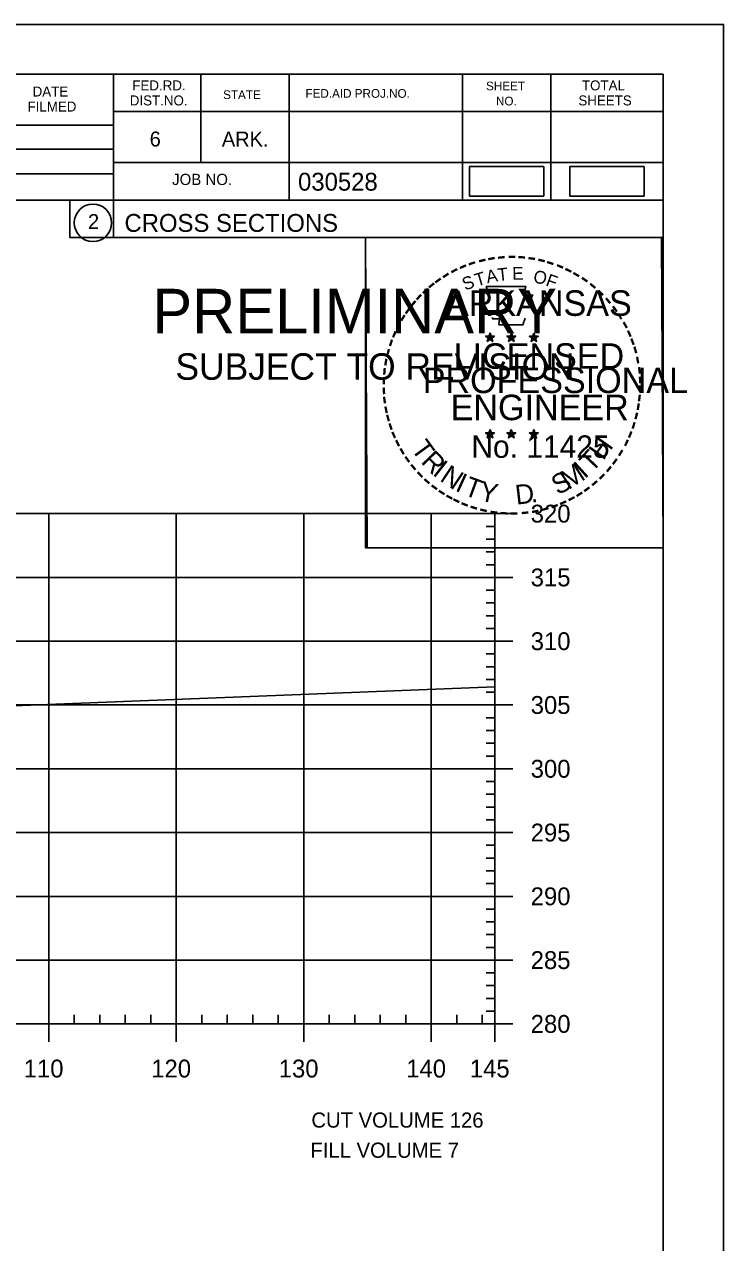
# Model space of a CAD drawing. Extents: x 1370843 to 1371177, y 380307 to 382654.
# Drawn here: x 1371121.8 to 1371176.6, y 382558.7 to 382654.2 of the extents above; entities that cross this region are included whole.
import ezdxf

# ---------------------------------------------------------------- set-up
doc = ezdxf.new("R2010")
doc.units = 0
for name, color, linetype in [('R_Axis', 7, 'Continuous'), ('R_Axis Annot', 7, 'Continuous'), ('R_Border', 7, 'Continuous'), ('R_Border Notes', 7, 'Continuous'), ('R_Border PE', 7, 'Continuous'), ('R_Border Prem', 7, 'Continuous'), ('R_Draft', 7, 'Continuous'), ('R_Exist Surface', 7, 'Continuous'), ('R_Grid', 7, 'Continuous'), ('R_No Plot', 7, 'Continuous')]:
    doc.layers.add(name, color=color, linetype=linetype)

msp = doc.modelspace()

# ---------------------------------------------------------------- linework, layer by layer
at = {"layer": 'R_Axis'}
for p, q in [((1371158.709, 382575.828), (1371158.709, 382615.828)), ((1371160.109, 382615.828), (1371158.709, 382615.828)), ((1371158.709, 382614.828), (1371158.009, 382614.828)), ((1371158.709, 382613.828), (1371158.009, 382613.828)), ((1371158.709, 382612.828), (1371158.009, 382612.828)), ((1371158.709, 382611.828), (1371158.009, 382611.828)), ((1371160.109, 382610.828), (1371158.709, 382610.828)), ((1371158.709, 382609.828), (1371158.009, 382609.828)), ((1371158.709, 382608.828), (1371158.009, 382608.828)), ((1371158.709, 382607.828), (1371158.009, 382607.828)), ((1371158.709, 382606.828), (1371158.009, 382606.828)), ((1371160.109, 382605.828), (1371158.709, 382605.828)), ((1371158.709, 382604.828), (1371158.009, 382604.828)), ((1371158.709, 382603.828), (1371158.009, 382603.828)), ((1371158.709, 382602.828), (1371158.009, 382602.828)), ((1371158.709, 382601.828), (1371158.009, 382601.828)), ((1371160.109, 382600.828), (1371158.709, 382600.828)), ((1371158.709, 382599.828), (1371158.009, 382599.828)), ((1371158.709, 382598.828), (1371158.009, 382598.828)), ((1371158.709, 382597.828), (1371158.009, 382597.828)), ((1371158.709, 382596.828), (1371158.009, 382596.828)), ((1371160.109, 382595.828), (1371158.709, 382595.828)), ((1371158.709, 382594.828), (1371158.009, 382594.828)), ((1371158.709, 382593.828), (1371158.009, 382593.828)), ((1371158.709, 382592.828), (1371158.009, 382592.828)), ((1371158.709, 382591.828), (1371158.009, 382591.828)), ((1371160.109, 382590.828), (1371158.709, 382590.828)), ((1371158.709, 382589.828), (1371158.009, 382589.828)), ((1371158.709, 382588.828), (1371158.009, 382588.828)), ((1371158.709, 382587.828), (1371158.009, 382587.828)), ((1371158.709, 382586.828), (1371158.009, 382586.828)), ((1371160.109, 382585.828), (1371158.709, 382585.828)), ((1371158.709, 382584.828), (1371158.009, 382584.828)), ((1371158.709, 382583.828), (1371158.009, 382583.828)), ((1371158.709, 382582.828), (1371158.009, 382582.828)), ((1371158.709, 382581.828), (1371158.009, 382581.828)), ((1371160.109, 382580.828), (1371158.709, 382580.828)), ((1371158.709, 382579.828), (1371158.009, 382579.828)), ((1371158.709, 382578.828), (1371158.009, 382578.828)), ((1371158.709, 382577.828), (1371158.009, 382577.828)), ((1371158.709, 382576.828), (1371158.009, 382576.828)), ((1370868.709, 382575.828), (1371158.709, 382575.828)), ((1371123.709, 382574.428), (1371123.709, 382575.828)), ((1371125.709, 382575.828), (1371125.709, 382576.528)), ((1371127.709, 382575.828), (1371127.709, 382576.528)), ((1371129.709, 382575.828), (1371129.709, 382576.528)), ((1371131.709, 382575.828), (1371131.709, 382576.528)), ((1371133.709, 382574.428), (1371133.709, 382575.828)), ((1371135.709, 382575.828), (1371135.709, 382576.528)), ((1371137.709, 382575.828), (1371137.709, 382576.528)), ((1371139.709, 382575.828), (1371139.709, 382576.528)), ((1371141.709, 382575.828), (1371141.709, 382576.528)), ((1371143.709, 382574.428), (1371143.709, 382575.828)), ((1371145.709, 382575.828), (1371145.709, 382576.528)), ((1371147.709, 382575.828), (1371147.709, 382576.528)), ((1371149.709, 382575.828), (1371149.709, 382576.528)), ((1371151.709, 382575.828), (1371151.709, 382576.528)), ((1371153.709, 382574.428), (1371153.709, 382575.828)), ((1371155.709, 382575.828), (1371155.709, 382576.528)), ((1371157.709, 382575.828), (1371157.709, 382576.528)), ((1371158.709, 382574.428), (1371158.709, 382575.828)), ((1371160.109, 382575.828), (1371158.709, 382575.828))]:
    msp.add_line(p, q, dxfattribs=at)
at = {"layer": 'R_Border'}
for p, q in [((1370855.709, 382650.288), (1371171.889, 382650.288)), ((1371128.789, 382650.288), (1371128.789, 382637.488)), ((1371135.629, 382650.288), (1371135.629, 382643.348)), ((1371142.569, 382650.288), (1371142.569, 382640.408)), ((1371156.149, 382650.288), (1371156.149, 382640.408)), ((1371163.089, 382650.288), (1371163.089, 382640.408)), ((1371171.889, 382444.828), (1371171.889, 382650.288)), ((1371171.889, 382647.348), (1371128.789, 382647.348)), ((1371171.889, 382647.368), (1371171.889, 382647.368)), ((1371089.629, 382646.268), (1371128.789, 382646.268)), ((1371089.629, 382644.408), (1371128.789, 382644.408)), ((1371171.889, 382643.348), (1371128.789, 382643.348)), ((1371131.749, 382643.348), (1371171.889, 382643.348)), ((1371089.629, 382642.468), (1371128.789, 382642.468)), ((1371171.889, 382640.408), (1371089.629, 382640.408)), ((1371128.789, 382637.488), (1371171.889, 382637.488))]:
    msp.add_line(p, q, dxfattribs=at)
msp.add_circle((1371127.176, 382638.624), 1.467, dxfattribs=at)
at = {"layer": 'R_Border PE'}
for p, q in [((1371157.974, 382629.743), (1371158.323, 382629.632)), ((1371157.974, 382629.743), (1371158.227, 382629.698)), ((1371157.974, 382629.743), (1371158.211, 382629.621)), ((1371158.107, 382629.335), (1371158.323, 382629.632)), ((1371158.107, 382629.335), (1371158.233, 382629.579)), ((1371158.107, 382629.335), (1371158.321, 382629.552)), ((1371158.323, 382629.997), (1371158.282, 382629.745)), ((1371158.536, 382629.335), (1371158.321, 382629.549)), ((1371158.323, 382629.632), (1371158.323, 382629.997)), ((1371158.323, 382629.997), (1371158.372, 382629.747)), ((1371158.67, 382629.743), (1371158.323, 382629.632)), ((1371158.536, 382629.335), (1371158.323, 382629.632)), ((1371158.67, 382629.743), (1371158.384, 382629.694)), ((1371158.536, 382629.335), (1371158.399, 382629.626)), ((1371158.67, 382629.743), (1371158.466, 382629.641)), ((1371159.644, 382629.743), (1371159.993, 382629.632)), ((1371159.644, 382629.743), (1371159.897, 382629.698)), ((1371159.644, 382629.743), (1371159.881, 382629.621)), ((1371159.777, 382629.335), (1371159.993, 382629.632)), ((1371159.777, 382629.335), (1371159.903, 382629.579)), ((1371159.777, 382629.335), (1371159.991, 382629.552)), ((1371159.993, 382629.997), (1371159.952, 382629.745)), ((1371160.206, 382629.335), (1371159.991, 382629.549)), ((1371159.993, 382629.632), (1371159.993, 382629.997)), ((1371159.993, 382629.997), (1371160.042, 382629.747)), ((1371160.34, 382629.743), (1371159.993, 382629.632)), ((1371160.206, 382629.335), (1371159.993, 382629.632)), ((1371160.34, 382629.743), (1371160.054, 382629.694)), ((1371160.206, 382629.335), (1371160.069, 382629.626)), ((1371160.34, 382629.743), (1371160.136, 382629.641)), ((1371161.408, 382629.731), (1371161.757, 382629.62)), ((1371161.408, 382629.731), (1371161.661, 382629.686)), ((1371161.408, 382629.731), (1371161.645, 382629.609)), ((1371161.541, 382629.323), (1371161.757, 382629.62)), ((1371161.541, 382629.323), (1371161.667, 382629.567)), ((1371161.541, 382629.323), (1371161.755, 382629.54)), ((1371161.757, 382629.985), (1371161.716, 382629.733)), ((1371161.97, 382629.323), (1371161.755, 382629.537)), ((1371161.757, 382629.62), (1371161.757, 382629.985)), ((1371161.757, 382629.985), (1371161.806, 382629.735)), ((1371162.104, 382629.731), (1371161.757, 382629.62)), ((1371161.97, 382629.323), (1371161.757, 382629.62)), ((1371162.104, 382629.731), (1371161.818, 382629.682)), ((1371161.97, 382629.323), (1371161.833, 382629.614)), ((1371162.104, 382629.731), (1371161.9, 382629.629)), ((1371158.319, 382622.424), (1371158.278, 382622.172)), ((1371158.319, 382622.059), (1371158.319, 382622.424)), ((1371158.319, 382622.424), (1371158.368, 382622.174)), ((1371159.988, 382622.424), (1371159.947, 382622.172)), ((1371159.988, 382622.059), (1371159.988, 382622.424)), ((1371159.988, 382622.424), (1371160.037, 382622.174)), ((1371157.97, 382622.17), (1371158.319, 382622.059)), ((1371157.97, 382622.17), (1371158.223, 382622.125)), ((1371157.97, 382622.17), (1371158.207, 382622.048)), ((1371158.103, 382621.762), (1371158.319, 382622.059)), ((1371158.103, 382621.762), (1371158.229, 382622.006)), ((1371158.103, 382621.762), (1371158.317, 382621.979)), ((1371158.532, 382621.762), (1371158.317, 382621.976)), ((1371158.666, 382622.17), (1371158.319, 382622.059)), ((1371158.532, 382621.762), (1371158.319, 382622.059)), ((1371158.666, 382622.17), (1371158.38, 382622.121)), ((1371158.532, 382621.762), (1371158.395, 382622.053)), ((1371158.666, 382622.17), (1371158.462, 382622.068)), ((1371159.639, 382622.17), (1371159.988, 382622.059)), ((1371159.639, 382622.17), (1371159.892, 382622.125)), ((1371159.639, 382622.17), (1371159.876, 382622.048)), ((1371159.772, 382621.762), (1371159.988, 382622.059)), ((1371159.772, 382621.762), (1371159.898, 382622.006)), ((1371159.772, 382621.762), (1371159.986, 382621.979)), ((1371160.201, 382621.762), (1371159.986, 382621.976)), ((1371160.335, 382622.17), (1371159.988, 382622.059)), ((1371160.201, 382621.762), (1371159.988, 382622.059)), ((1371160.335, 382622.17), (1371160.049, 382622.121)), ((1371160.201, 382621.762), (1371160.064, 382622.053)), ((1371160.335, 382622.17), (1371160.131, 382622.068)), ((1371161.406, 382622.16), (1371161.755, 382622.049)), ((1371161.406, 382622.16), (1371161.659, 382622.115)), ((1371161.406, 382622.16), (1371161.643, 382622.038)), ((1371161.539, 382621.752), (1371161.755, 382622.049)), ((1371161.539, 382621.752), (1371161.665, 382621.996)), ((1371161.539, 382621.752), (1371161.753, 382621.969)), ((1371161.755, 382622.414), (1371161.714, 382622.162)), ((1371161.968, 382621.752), (1371161.753, 382621.966)), ((1371161.755, 382622.049), (1371161.755, 382622.414)), ((1371161.755, 382622.414), (1371161.804, 382622.164)), ((1371162.102, 382622.16), (1371161.755, 382622.049)), ((1371161.968, 382621.752), (1371161.755, 382622.049)), ((1371162.102, 382622.16), (1371161.816, 382622.111)), ((1371161.968, 382621.752), (1371161.831, 382622.043)), ((1371162.102, 382622.16), (1371161.898, 382622.058))]:
    msp.add_line(p, q, dxfattribs=at)
for points in [[(1371158.015, 382633.621), (1371158.284, 382632.794)], [(1371161.526, 382632.699), (1371161.668, 382632.983), (1371160.983, 382632.959), (1371161.131, 382633.621), (1371158.015, 382633.621)], [(1371158.507, 382631.198), (1371158.507, 382631.111), (1371159.07, 382631.092), (1371159.016, 382630.619), (1371160.886, 382630.619), (1371161.087, 382631.155)], [(1371158.323, 382629.997), (1371158.536, 382629.335), (1371157.974, 382629.743), (1371158.67, 382629.743), (1371158.107, 382629.335), (1371158.323, 382629.997)], [(1371159.993, 382629.997), (1371160.206, 382629.335), (1371159.644, 382629.743), (1371160.34, 382629.743), (1371159.777, 382629.335), (1371159.993, 382629.997)], [(1371161.757, 382629.985), (1371161.97, 382629.323), (1371161.408, 382629.731), (1371162.104, 382629.731), (1371161.541, 382629.323), (1371161.757, 382629.985)], [(1371158.319, 382622.424), (1371158.532, 382621.762), (1371157.97, 382622.17), (1371158.666, 382622.17), (1371158.103, 382621.762), (1371158.319, 382622.424)], [(1371159.988, 382622.424), (1371160.201, 382621.762), (1371159.639, 382622.17), (1371160.335, 382622.17), (1371159.772, 382621.762), (1371159.988, 382622.424)], [(1371161.755, 382622.414), (1371161.968, 382621.752), (1371161.406, 382622.16), (1371162.102, 382622.16), (1371161.539, 382621.752), (1371161.755, 382622.414)]]:
    msp.add_lwpolyline(points, dxfattribs=at)
for centre, radius in [((1371158.322, 382629.631), 0.172), ((1371158.322, 382629.631), 0.145), ((1371158.322, 382629.631), 0.116), ((1371158.322, 382629.631), 0.0991), ((1371158.322, 382629.631), 0.0747), ((1371158.322, 382629.631), 0.0495), ((1371158.322, 382629.631), 0.0296), ((1371159.992, 382629.631), 0.172), ((1371159.992, 382629.631), 0.145), ((1371159.992, 382629.631), 0.116), ((1371159.992, 382629.631), 0.0991), ((1371159.992, 382629.631), 0.0747), ((1371159.992, 382629.631), 0.0495), ((1371159.992, 382629.631), 0.0296), ((1371161.756, 382629.619), 0.172), ((1371161.756, 382629.619), 0.145), ((1371161.756, 382629.619), 0.116), ((1371161.756, 382629.619), 0.0991), ((1371161.756, 382629.619), 0.0747), ((1371161.756, 382629.619), 0.0495), ((1371161.756, 382629.619), 0.0296), ((1371158.318, 382622.058), 0.172), ((1371158.318, 382622.058), 0.145), ((1371158.318, 382622.058), 0.116), ((1371158.318, 382622.058), 0.0991), ((1371158.318, 382622.058), 0.0747), ((1371158.318, 382622.058), 0.0495), ((1371158.318, 382622.058), 0.0296), ((1371159.987, 382622.058), 0.172), ((1371159.987, 382622.058), 0.145), ((1371159.987, 382622.058), 0.116), ((1371159.987, 382622.058), 0.0991), ((1371159.987, 382622.058), 0.0747), ((1371159.987, 382622.058), 0.0495), ((1371159.987, 382622.058), 0.0296), ((1371161.754, 382622.048), 0.172), ((1371161.754, 382622.048), 0.145), ((1371161.754, 382622.048), 0.116), ((1371161.754, 382622.048), 0.0991), ((1371161.754, 382622.048), 0.0747), ((1371161.754, 382622.048), 0.0495), ((1371161.754, 382622.048), 0.0296)]:
    msp.add_circle(centre, radius, dxfattribs=at)
at = {"layer": 'R_Draft'}
for points in [[(1371156.702, 382640.723), (1371162.536, 382640.723), (1371162.536, 382643.033), (1371156.702, 382643.033)], [(1371164.572, 382640.723), (1371170.406, 382640.723), (1371170.406, 382643.033), (1371164.572, 382643.033)]]:
    msp.add_lwpolyline(points, close=True, dxfattribs=at)
at = {"layer": 'R_Exist Surface'}
msp.add_line((1371098.98, 382599.884), (1371158.709, 382602.255), dxfattribs=at)
at = {"layer": 'R_Grid'}
for p, q in [((1370868.709, 382615.828), (1371158.709, 382615.828)), ((1371123.709, 382575.828), (1371123.709, 382615.828)), ((1371133.709, 382575.828), (1371133.709, 382615.828)), ((1371143.709, 382575.828), (1371143.709, 382615.828)), ((1371153.709, 382575.828), (1371153.709, 382615.828)), ((1371158.709, 382575.828), (1371158.709, 382615.828)), ((1370868.709, 382610.828), (1371158.709, 382610.828)), ((1370868.709, 382605.828), (1371158.709, 382605.828)), ((1370868.709, 382600.828), (1371158.709, 382600.828)), ((1370868.709, 382595.828), (1371158.709, 382595.828)), ((1370868.709, 382590.828), (1371158.709, 382590.828)), ((1370868.709, 382585.828), (1371158.709, 382585.828)), ((1370868.709, 382580.828), (1371158.709, 382580.828)), ((1370868.709, 382575.828), (1371158.709, 382575.828))]:
    msp.add_line(p, q, dxfattribs=at)
at = {"layer": 'R_No Plot'}
for p, q in [((1370843.308, 382654.183), (1371176.642, 382654.183)), ((1371147.923, 382615.033), (1371147.923, 382615.033))]:
    msp.add_line(p, q, dxfattribs=at)
for points in [[(1370843.302, 382654.183), (1371176.642, 382654.183), (1371176.642, 382440.845), (1370843.302, 382440.845)], [(1371089.629, 382650.288), (1371089.629, 382640.408), (1371125.361, 382640.408), (1371125.361, 382637.488), (1371148.561, 382637.488), (1371148.561, 382613.156), (1371171.889, 382613.156), (1371171.889, 382444.828), (1370855.709, 382444.828), (1370855.709, 382650.288)], [(1371148.561, 382637.488), (1371171.768, 382637.488), (1371171.889, 382613.156), (1371148.681, 382613.156)]]:
    msp.add_lwpolyline(points, close=True, dxfattribs=at)

# ---------------------------------------------------------------- texts
at = {"layer": 'R_Axis Annot'}
for s, p in [('320', (1371161.509, 382615.128)), ('315', (1371161.509, 382610.128)), ('310', (1371161.509, 382605.128)), ('305', (1371161.509, 382600.128)), ('300', (1371161.509, 382595.128)), ('295', (1371161.509, 382590.128)), ('290', (1371161.509, 382585.128)), ('285', (1371161.509, 382580.128)), ('280', (1371161.509, 382575.128)), ('110', (1371121.748, 382571.628)), ('120', (1371131.748, 382571.628)), ('130', (1371141.748, 382571.628)), ('140', (1371151.748, 382571.628)), ('145', (1371156.735, 382571.628))]:
    msp.add_text(s, height=1.4, dxfattribs=at).set_placement(p)
at = {"layer": 'R_Border'}
for s, height, p in [('DATE', 0.7819, (1371122.449, 382648.528)), ('FED.RD.', 0.7819, (1371130.269, 382649.008)), ('SHEET', 0.684, (1371158.009, 382649.008)), ('TOTAL', 0.7819, (1371165.529, 382649.008)), ('DIST.NO.', 0.7819, (1371130.069, 382647.828)), ('STATE', 0.684, (1371137.389, 382648.328)), ('FED.AID PROJ.NO.', 0.684, (1371143.849, 382648.428)), ('NO.', 0.684, (1371158.789, 382647.828)), ('SHEETS', 0.7819, (1371165.249, 382647.828)), ('FILMED', 0.7819, (1371122.049, 382647.348)), ('6', 1.172, (1371131.629, 382644.608)), ('ARK.', 1.1723, (1371137.289, 382644.608)), ('JOB NO.', 0.8792, (1371133.389, 382641.588)), ('030528', 1.4, (1371143.265, 382641.148)), ('2', 1.172, (1371126.793, 382638.137)), ('CROSS SECTIONS', 1.4, (1371129.653, 382637.918))]:
    msp.add_text(s, height=height, rotation=360, dxfattribs=at).set_placement(p)
at = {"layer": 'R_Border Notes'}
for s, p in [('CUT VOLUME 126', (1371144.31, 382567.697)), ('FILL VOLUME 7', (1371144.235, 382565.334))]:
    msp.add_text(s, height=1.18747, dxfattribs=at).set_placement(p)
at = {"layer": 'R_Border PE'}
for s, height, rotation, p in [('-', 1.6, 13.63015, (1371157.513, 382634.989)), ('-', 1.6, 10.21935, (1371158.191, 382635.151)), ('-', 1.6, 5.89682, (1371158.92, 382635.261)), ('-', 1.6, 0.18623, (1371159.692, 382635.333)), ('-', 1.6, 357.74304, (1371160.415, 382635.32)), ('-', 1.6, 352.16172, (1371161.159, 382635.264)), ('-', 1.6, 347.20489, (1371161.878, 382635.15)), ('-', 1.6, 28.79182, (1371155.496, 382634.162)), ('-', 1.6, 24.30721, (1371156.129, 382634.479)), ('-', 1.6, 19.17608, (1371156.763, 382634.748)), ('A', 1, 11.21318, (1371158.11, 382633.881)), ('T', 1, 6.02276, (1371158.959, 382634.047)), ('E', 1, 0.83234, (1371160.064, 382634.157)), ('O', 1, 350.4515, (1371161.668, 382633.947)), ('-', 1.6, 342.3362, (1371162.513, 382634.995)), ('-', 1.6, 337.85509, (1371163.248, 382634.772)), ('-', 1.6, 334.12109, (1371163.879, 382634.501)), ('-', 1.6, 38.95066, (1371153.845, 382633.019)), ('-', 1.6, 36.23174, (1371154.321, 382633.397)), ('-', 1.6, 34.06357, (1371154.899, 382633.792)), ('S', 1, 21.59401, (1371156.37, 382633.299)), ('T', 1, 16.4036, (1371157.284, 382633.63)), ('F', 1, 340.07066, (1371162.622, 382633.719)), ('-', 1.6, 329.64089, (1371164.458, 382634.218)), ('-', 1.6, 325.86266, (1371165.101, 382633.857)), ('-', 1.6, 320.52971, (1371165.711, 382633.431)), ('-', 1.6, 48.42305, (1371152.964, 382632.124)), ('-', 1.6, 42.96224, (1371153.412, 382632.602)), ('ARKANSAS', 2, 360, (1371154.868, 382631.333)), ('-', 1.6, 315.57859, (1371166.31, 382632.943)), ('-', 1.6, 54.23247, (1371152.148, 382631.071)), ('-', 1.6, 50.61417, (1371152.561, 382631.638)), ('-', 1.6, 309.87973, (1371166.879, 382632.393)), ('-', 1.6, 306.65218, (1371167.404, 382631.791)), ('-', 1.6, 58.07063, (1371151.823, 382630.544)), ('-', 1.4, 303.67529, (1371167.89, 382631.223)), ('-', 1.6, 67.77427, (1371151.251, 382629.319)), ('-', 1.6, 62.87135, (1371151.51, 382629.93)), ('-', 1.6, 299.66835, (1371168.209, 382630.616)), ('-', 1.6, 294.66279, (1371168.533, 382630.004)), ('-', 1.6, 72.39447, (1371151.032, 382628.689)), ('LICENSED', 2, 360, (1371155.465, 382627.184)), ('DWB', 0.01, 360, (1371158.31, 382629.627)), ('DWB', 0.01, 360, (1371159.98, 382629.627)), ('DWB', 0.01, 360, (1371161.744, 382629.616)), ('-', 1.6, 290.57283, (1371168.79, 382629.427)), ('-', 1.6, 75.46096, (1371150.835, 382627.975)), ('-', 1.6, 285.12326, (1371169.024, 382628.847)), ('-', 1.6, 85.18634, (1371150.627, 382626.571)), ('-', 1.6, 81.20126, (1371150.703, 382627.262)), ('PROFESSIONAL', 2, 360, (1371153.042, 382625.28)), ('-', 1.6, 280.54934, (1371169.224, 382628.105)), ('-', 1.6, 276.59616, (1371169.386, 382627.337)), ('-', 1.6, 89.06224, (1371150.602, 382625.87)), ('-', 1.6, 274.33011, (1371169.446, 382626.615)), ('-', 1.6, 94.19588, (1371150.637, 382625.145)), ('-', 1.6, 269.94067, (1371169.48, 382625.983)), ('-', 1.6, 98.94793, (1371150.709, 382624.478)), ('ENGINEER', 2, 360, (1371155.229, 382623.155)), ('-', 1.6, 260.99529, (1371169.39, 382624.663)), ('-', 1.6, 263.5172, (1371169.461, 382625.317)), ('-', 1.6, 101.71495, (1371150.844, 382623.745)), ('-', 1.6, 105.45785, (1371151.006, 382623.15)), ('-', 1.6, 255.7626, (1371169.28, 382623.985)), ('-', 1.6, 109.08742, (1371151.221, 382622.519)), ('-', 1.6, 252.86809, (1371169.099, 382623.265)), ('-', 1.6, 114.06432, (1371151.475, 382621.923)), ('-', 1.6, 115.72885, (1371151.78, 382621.305)), ('T', 1.54, 306.04056, (1371152.078, 382620.897)), ('No. 11425', 1.757, 360, (1371156.856, 382620.204)), ('DWB', 0.01, 360, (1371158.306, 382622.054)), ('DWB', 0.01, 360, (1371159.975, 382622.054)), ('DWB', 0.01, 360, (1371161.742, 382622.044)), ('H', 1.54, 54.60883, (1371167.199, 382619.933)), ('-', 1.6, 244.61971, (1371168.614, 382621.963)), ('-', 1.6, 247.88866, (1371168.876, 382622.592)), ('-', 1.6, 120.44712, (1371152.137, 382620.719)), ('R', 1.54, 314.00497, (1371152.841, 382619.85)), ('T', 1.54, 46.64442, (1371166.309, 382618.99)), ('-', 1.6, 239.07125, (1371168.22, 382621.211)), ('-', 1.6, 125.89344, (1371152.54, 382620.158)), ('-', 1.6, 130.71812, (1371153.002, 382619.606)), ('I', 1.54, 321.96938, (1371153.741, 382618.918)), ('N', 1.54, 326.50021, (1371154.309, 382618.446)), ('M', 1.54, 32.65632, (1371164.463, 382617.665)), ('I', 1.54, 42.11359, (1371165.747, 382618.512)), ('-', 1.6, 231.25377, (1371167.388, 382619.992)), ('-', 1.6, 233.84524, (1371167.818, 382620.558)), ('-', 1.6, 134.22381, (1371153.519, 382619.061)), ('-', 1.6, 138.93382, (1371154.044, 382618.597)), ('I', 1.54, 335.36034, (1371155.517, 382617.66)), ('T', 1.54, 339.89117, (1371156.178, 382617.333)), ('S', 1.54, 26.9312, (1371163.624, 382617.259)), ('-', 1.6, 225.76533, (1371166.909, 382619.428)), ('-', 1.6, 144.64634, (1371154.6, 382618.191)), ('-', 1.6, 148.08978, (1371155.161, 382617.82)), ('Y', 1.54, 347.85558, (1371157.395, 382616.887)), ('D', 1.54, 6.39691, (1371160.38, 382616.529)), ('-', 1.6, 215.73633, (1371165.838, 382618.447)), ('-', 1.6, 221.08509, (1371166.387, 382618.919)), ('-', 1.6, 151.57039, (1371155.74, 382617.495)), ('-', 1.6, 154.60019, (1371156.262, 382617.248)), ('-', 1.6, 158.56121, (1371156.886, 382616.994)), ('.', 1.54, 13.76417, (1371161.572, 382616.656)), ('-', 1.6, 204.25161, (1371164.122, 382617.395)), ('-', 1.6, 207.35684, (1371164.746, 382617.714)), ('-', 1.6, 212.24909, (1371165.304, 382618.06)), ('-', 1.6, 162.79826, (1371157.573, 382616.781)), ('-', 1.6, 167.55551, (1371158.288, 382616.617)), ('-', 1.6, 173.11546, (1371159.06, 382616.507)), ('-', 1.6, 176.51827, (1371159.808, 382616.454)), ('-', 1.6, 181.59176, (1371160.552, 382616.473)), ('-', 1.6, 185.81666, (1371161.361, 382616.549)), ('-', 1.6, 191.28576, (1371162.097, 382616.681)), ('-', 1.6, 195.47429, (1371162.826, 382616.88)), ('-', 1.6, 200.71842, (1371163.503, 382617.122))]:
    msp.add_text(s, height=height, rotation=rotation, dxfattribs=at).set_placement(p)
at = {"layer": 'R_Border Prem'}
for s, height, p in [('PRELIMINARY', 3.5, (1371131.84, 382629.951)), ('DWB', 0.01, (1371132.587, 382631.8)), ('SUBJECT TO REVISION', 2.07511, (1371133.649, 382626.322))]:
    msp.add_text(s, height=height, rotation=360, dxfattribs=at).set_placement(p)

doc.saveas('drawing.dxf')
